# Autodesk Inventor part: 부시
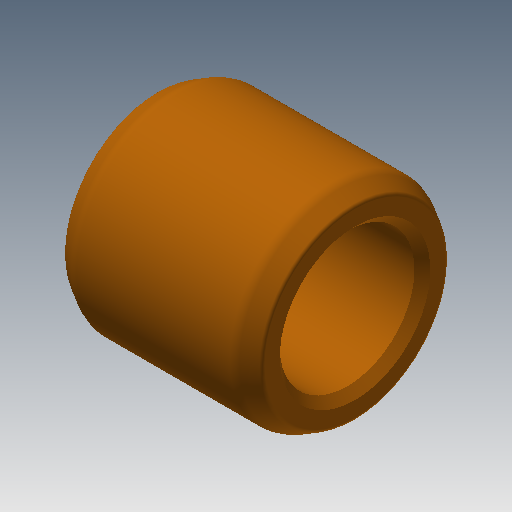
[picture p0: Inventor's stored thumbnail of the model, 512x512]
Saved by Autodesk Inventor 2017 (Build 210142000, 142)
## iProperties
Created: 2018-11
Part Number: 부시
Material: 강철, 연강
Document SubType Name: Modeling
Designer: mduedu
Density: 1 g/cm^3
Appearance: Orange
Author: mduedu
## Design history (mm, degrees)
sketch "스케치1"
  geometry: C1 r 8.5 at (0, 0); C2 r 13 at (0, 0); 1 further point
  constraints: 2 centre point, 2 coincident
  dimensions: "d0" = 17 diameter of C1; "d1" = 26 diameter of C2
extrude "돌출1" new body sketch "스케치1" distance "d2" = 25; taper "d3" = 0 deg
chamfer "모따기4" distance "d14" = 1; stored, may be unused: second distance "d15" = 2, angle "d16" = 15 deg
chamfer "모따기5" distance "d17" = 2.3; stored, may be unused: second distance "d18" = 2, angle "d19" = 30 deg
chamfer "모따기6" distance "d20" = 2.3; stored, may be unused: second distance "d21" = 2, angle "d22" = 30 deg
fillet "모깎기2" dims "d23" = 2, "d24" = 0.5
fillet "모깎기3" dims "d25" = 2, "d26" = 0.5
node "솔리드1"
